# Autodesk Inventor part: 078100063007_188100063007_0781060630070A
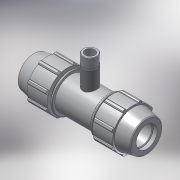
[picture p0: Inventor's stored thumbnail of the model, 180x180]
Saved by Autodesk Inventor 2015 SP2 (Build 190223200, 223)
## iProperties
Created: 2017-02
Part Number: 078100063007_188100063007_0781060630070A
Material: PVC-Piping
Description: PLASSON COUPLER WITH RISER 63-3/4"
Document SubType Name: Modeling
Designer: KIM
Mass: 92.6774 g
Surface Area: 199.44 cm^2
Volume: 66.1981 cm^3
Density: 1.4 g/cm^3
Appearance: Smooth - White
Author: Кирилл
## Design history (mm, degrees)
derived "07810.ipt"
feature "Solid1::07810.ipt"
feature "Solid2::07810.ipt"
tag "TaggingFeature1"
body "Solid1"
other parameters: "d2" = 63, "d4" = 11.25, "d5" = 32.4, "d7" = 113, "d11" = 4.5, "d13" = 120 deg, "d14" = 81.9, "d15" = 12 deg, "d16" = 98.31, "d18" = 3.15, "d19" = 35 deg, "d20" = 17.5 deg, "d21" = 105.09, "d23" = 0, "d25" = 360 deg, "d27" = 2.26, "d33" = 1.26, "d42" = 48.6, "d43" = 3.39, "d46" = 1.89, "d68" = 4.5, "d72" = 95, "d73" = 26.441, "d74" = 18, "d76" = 18.5087, "d77" = 21.6, "d80" = 0.79323, "d91" = 84.75, "d95" = 56.7, "d101" = 0, "d103" = 0, "d105" = 0, "d106" = 26.96982, "d_" = 63, "E_" = 113, "A_" = 95, "l_2" = 18, "R_" = 26.441
